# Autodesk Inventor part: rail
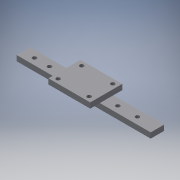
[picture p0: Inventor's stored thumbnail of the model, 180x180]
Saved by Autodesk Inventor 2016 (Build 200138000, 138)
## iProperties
Created: 2016-02
Part Number: rail
Material: Generic
Document SubType Name: Modeling
Designer: Juha-Pekka
Density: 1 g/cm^3
Appearance: Default
Author: Juha-Pekka
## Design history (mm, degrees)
sketch "Sketch1"
  geometry: L1 (0, 0)-(100, 0); L2 (100, 0)-(100, 10); L3 (100, 10)-(0, 10); L4 (0, 10)-(0, 0)
  constraints: 8 end point, 2 parallel, 1 horizontal, 1 perpendicular
  dimensions: "d0" = 100 distance of L3.end L2.end; "d1" = 10 distance of L2.end L1.end
extrude "Extrusion1" new body sketch "Sketch1" distance "d2" = 4; taper "d3" = 0 deg
sketch "Sketch2"
  geometry: L1 (30.991, 16.701)-(62.102, 16.701); L2 (62.102, 16.701)-(62.102, -7.175); L3 (62.102, -7.175)-(30.991, -7.175); L4 (30.991, -7.175)-(30.991, 16.701); 1 further point
  constraints: 8 end point, 2 parallel, 1 horizontal, 1 perpendicular
extrude "Extrusion2" join sketch "Sketch2" distance "d4" = 4; taper "d5" = 0 deg
hole "Hole1" diameter "d8" = 3; stored, may be unused: countersink angle "d12" = 90 deg, drill point angle "d14" = 118 deg; dims "d6" = 10, "d7" = 10, "d9" = 6, "d10" = 4, "d11" = 2, "d13" = 8
hole "Hole2" diameter "d17" = 3; stored, may be unused: countersink angle "d21" = 90 deg, drill point angle "d23" = 118 deg; dims "d15" = 10, "d16" = 10, "d18" = 6, "d19" = 4, "d20" = 2, "d22" = 8
hole "Hole3" diameter "d26" = 3; stored, may be unused: countersink angle "d30" = 90 deg, drill point angle "d32" = 118 deg; dims "d24" = 10, "d25" = 10, "d27" = 6, "d28" = 4, "d29" = 2, "d31" = 8
hole "Hole4" diameter "d35" = 3; stored, may be unused: countersink angle "d39" = 90 deg, drill point angle "d41" = 118 deg; dims "d33" = 10, "d34" = 10, "d36" = 6, "d37" = 4, "d38" = 2, "d40" = 4
hole "Hole5" diameter "d44" = 3; stored, may be unused: countersink angle "d48" = 90 deg, drill point angle "d50" = 118 deg; dims "d42" = 10, "d43" = 10, "d45" = 6, "d46" = 4, "d47" = 2, "d49" = 8
hole "Hole6" diameter "d53" = 3; stored, may be unused: countersink angle "d57" = 90 deg, drill point angle "d59" = 118 deg; dims "d51" = 10, "d52" = 10, "d54" = 6, "d55" = 4, "d56" = 2, "d58" = 8
hole "Hole7" diameter "d62" = 3; stored, may be unused: countersink angle "d66" = 90 deg, drill point angle "d68" = 118 deg; dims "d60" = 10, "d61" = 10, "d63" = 6, "d64" = 4, "d65" = 2, "d67" = 8
hole "Hole8" diameter "d71" = 3; stored, may be unused: countersink angle "d75" = 90 deg, drill point angle "d77" = 118 deg; dims "d69" = 10, "d70" = 10, "d72" = 6, "d73" = 4, "d74" = 2, "d76" = 8
body "Solid1"
